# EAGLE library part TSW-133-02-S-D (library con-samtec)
THROUGH-HOLE .025" SQ POST HEADER Source: Samtec TSW.pdf
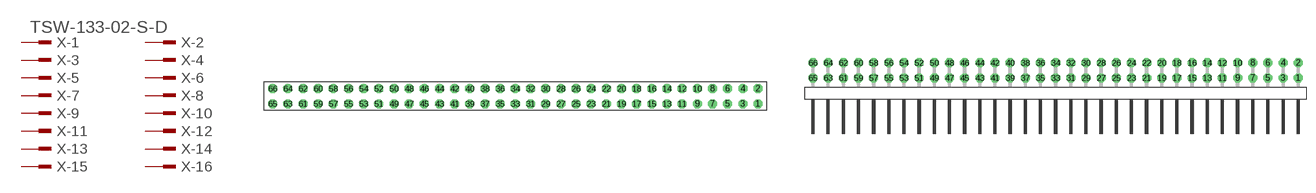
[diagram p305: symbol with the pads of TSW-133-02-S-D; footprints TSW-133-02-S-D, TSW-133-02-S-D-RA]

Designator prefix X; gates -1=MPINV -2=MPIN -3=MPIN -4=MPIN -5=MPIN -6=MPIN -7=MPIN -8=MPIN -9=MPIN -10=MPIN -11=MPIN -12=MPIN -13=MPIN -14=MPIN -15=MPIN -16=MPIN -17=MPIN -18=MPIN -19=MPIN -20=MPIN -21=MPIN -22=MPIN -23=MPIN -24=MPIN -25=MPIN -26=MPIN -27=MPIN -28=MPIN -29=MPIN -30=MPIN -31=MPIN -32=MPIN -33=MPIN -34=MPIN -35=MPIN -36=MPIN -37=MPIN -38=MPIN -39=MPIN -40=MPIN -41=MPIN -42=MPIN -43=MPIN -44=MPIN -45=MPIN -46=MPIN -47=MPIN -48=MPIN -49=MPIN -50=MPIN -51=MPIN -52=MPIN -53=MPIN -54=MPIN -55=MPIN -56=MPIN -57=MPIN -58=MPIN -59=MPIN -60=MPIN -61=MPIN -62=MPIN -63=MPIN -64=MPIN -65=MPIN -66=MPIN

## TSW-133-02-S-D (OC_FARNELL: unknown; OC_NEWARK: unknown)  [TSW-133-02-S-D]
1  -1:1  pas
2  -2:1  pas
3  -3:1  pas
4  -4:1  pas
5  -5:1  pas
6  -6:1  pas
7  -7:1  pas
8  -8:1  pas
9  -9:1  pas
10  -10:1  pas
11  -11:1  pas
12  -12:1  pas
13  -13:1  pas
14  -14:1  pas
15  -15:1  pas
16  -16:1  pas
17  -17:1  pas
18  -18:1  pas
19  -19:1  pas
20  -20:1  pas
21  -21:1  pas
22  -22:1  pas
23  -23:1  pas
24  -24:1  pas
25  -25:1  pas
26  -26:1  pas
27  -27:1  pas
28  -28:1  pas
29  -29:1  pas
30  -30:1  pas
31  -31:1  pas
32  -32:1  pas
33  -33:1  pas
34  -34:1  pas
35  -35:1  pas
36  -36:1  pas
37  -37:1  pas
38  -38:1  pas
39  -39:1  pas
40  -40:1  pas
41  -41:1  pas
42  -42:1  pas
43  -43:1  pas
44  -44:1  pas
45  -45:1  pas
46  -46:1  pas
47  -47:1  pas
48  -48:1  pas
49  -49:1  pas
50  -50:1  pas
51  -51:1  pas
52  -52:1  pas
53  -53:1  pas
54  -54:1  pas
55  -55:1  pas
56  -56:1  pas
57  -57:1  pas
58  -58:1  pas
59  -59:1  pas
60  -60:1  pas
61  -61:1  pas
62  -62:1  pas
63  -63:1  pas
64  -64:1  pas
65  -65:1  pas
66  -66:1  pas

## TSW-133-02-S-D-RA (OC_FARNELL: unknown; OC_NEWARK: unknown)  [TSW-133-02-S-D-RA]
Pads as for TSW-133-02-S-D

## Footprint TSW-133-02-S-D (pad centres in mm)
THROUGH-HOLE .025" SQ POST HEADER Source: Samtec TSW.pdf
drill 1 pad 1.5 octagon: 1 40.64,-1.27; 2 40.64,1.27; 3 38.1,-1.27; 4 38.1,1.27; 5 35.56,-1.27; 6 35.56,1.27; 7 33.02,-1.27; 8 33.02,1.27; 9 30.48,-1.27; 10 30.48,1.27; 11 27.94,-1.27; 12 27.94,1.27; 13 25.4,-1.27; 14 25.4,1.27; 15 22.86,-1.27; 16 22.86,1.27; 17 20.32,-1.27; 18 20.32,1.27; 19 17.78,-1.27; 20 17.78,1.27; 21 15.24,-1.27; 22 15.24,1.27; 23 12.7,-1.27; 24 12.7,1.27; 25 10.16,-1.27; 26 10.16,1.27; 27 7.62,-1.27; 28 7.62,1.27; 29 5.08,-1.27; 30 5.08,1.27; 31 2.54,-1.27; 32 2.54,1.27; 33 0,-1.27; 34 0,1.27; 35 -2.54,-1.27; 36 -2.54,1.27; 37 -5.08,-1.27; 38 -5.08,1.27; 39 -7.62,-1.27; 40 -7.62,1.27; 41 -10.16,-1.27; 42 -10.16,1.27; 43 -12.7,-1.27; 44 -12.7,1.27; 45 -15.24,-1.27; 46 -15.24,1.27; 47 -17.78,-1.27; 48 -17.78,1.27; 49 -20.32,-1.27; 50 -20.32,1.27; 51 -22.86,-1.27; 52 -22.86,1.27; 53 -25.4,-1.27; 54 -25.4,1.27; 55 -27.94,-1.27; 56 -27.94,1.27; 57 -30.48,-1.27; 58 -30.48,1.27; 59 -33.02,-1.27; 60 -33.02,1.27; 61 -35.56,-1.27; 62 -35.56,1.27; 63 -38.1,-1.27; 64 -38.1,1.27; 65 -40.64,-1.27; 66 -40.64,1.27

## Footprint TSW-133-02-S-D-RA (pad centres in mm)
THROUGH-HOLE .025" SQ POST HEADER Source: Samtec TSW.pdf
drill 1 pad 1.5 octagon: 1 40.64,1.524; 2 40.64,4.064; 3 38.1,1.524; 4 38.1,4.064; 5 35.56,1.524; 6 35.56,4.064; 7 33.02,1.524; 8 33.02,4.064; 9 30.48,1.524; 10 30.48,4.064; 11 27.94,1.524; 12 27.94,4.064; 13 25.4,1.524; 14 25.4,4.064; 15 22.86,1.524; 16 22.86,4.064; 17 20.32,1.524; 18 20.32,4.064; 19 17.78,1.524; 20 17.78,4.064; 21 15.24,1.524; 22 15.24,4.064; 23 12.7,1.524; 24 12.7,4.064; 25 10.16,1.524; 26 10.16,4.064; 27 7.62,1.524; 28 7.62,4.064; 29 5.08,1.524; 30 5.08,4.064; 31 2.54,1.524; 32 2.54,4.064; 33 0,1.524; 34 0,4.064; 35 -2.54,1.524; 36 -2.54,4.064; 37 -5.08,1.524; 38 -5.08,4.064; 39 -7.62,1.524; 40 -7.62,4.064; 41 -10.16,1.524; 42 -10.16,4.064; 43 -12.7,1.524; 44 -12.7,4.064; 45 -15.24,1.524; 46 -15.24,4.064; 47 -17.78,1.524; 48 -17.78,4.064; 49 -20.32,1.524; 50 -20.32,4.064; 51 -22.86,1.524; 52 -22.86,4.064; 53 -25.4,1.524; 54 -25.4,4.064; 55 -27.94,1.524; 56 -27.94,4.064; 57 -30.48,1.524; 58 -30.48,4.064; 59 -33.02,1.524; 60 -33.02,4.064; 61 -35.56,1.524; 62 -35.56,4.064; 63 -38.1,1.524; 64 -38.1,4.064; 65 -40.64,1.524; 66 -40.64,4.064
